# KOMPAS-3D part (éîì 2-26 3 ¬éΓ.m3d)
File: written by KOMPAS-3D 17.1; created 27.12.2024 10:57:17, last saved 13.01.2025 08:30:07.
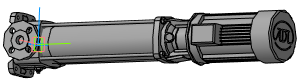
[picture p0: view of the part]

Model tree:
1. Операция без истории:4  (labels: ВМН 2-26 3,0 кВт)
